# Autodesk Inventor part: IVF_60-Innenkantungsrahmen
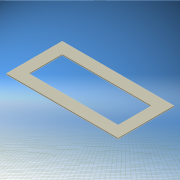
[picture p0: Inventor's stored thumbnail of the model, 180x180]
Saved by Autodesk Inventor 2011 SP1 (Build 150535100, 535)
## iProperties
Created: 2011-05
Part Number: IVF_60-Innenkantungsrahmen
Material: Standard
Document SubType Name: Blech
Designer: Gawin
Mass: 20.8 g
Surface Area: 228.8 cm^2
Volume: 20.8 cm^3
Density: 1 g/cm^3
Sheet Metal Rule: Standard_mm
Sheet Metal Width: 0,000 mm
Sheet Metal Length: 0,000 mm
Sheet Metal Area: 0,000 mm^2
Author: Gawin
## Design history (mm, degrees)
node "Fläche1"
  sketch "Skizze1"
    geometry: L1 (-100, -50)-(100, -50); L2 (100, -50)-(100, 50); L3 (100, 50)-(-100, 50); L4 (-100, 50)-(-100, -50); L5 (-80, 30)-(80, 30); L6 (80, 30)-(80, -30); L7 (80, -30)-(-80, -30); L8 (-80, -30)-(-80, 30); 5 further points
    constraints: 16 end point, 6 perpendicular, 4 midpoint, 2 horizontal, 2 horizontal alignment, 2 vertical alignment
    dimensions: "d0" = 200 distance of L2.end L3.end; "d1" = 100 distance of L3.end L1.start; "d2" = 20 distance between parallel lines of L5 L3; "d3" = 20 distance between parallel lines of L8 L4 (= d2)
node "Konturlasche1"
  sketch "Skizze2"
    geometry: L1 (80, 0)-(80, -12); L2 (80, -12)-(71, -12); 1 further point
    constraints: 4 end point, 1 perpendicular, 1 vertical
    dimensions: "d5" = 12 distance of L1.start L1.end; "d6" = 9 distance of L1.end L2.end
mirror "Spiegeln1"
node "Abwicklung1"
node "Lasche1"
node "Lasche2"
mirror "Spiegeln2"
node "Zurückfaltung1"
node "Volumenkörper1"
feature "Grobblech1" dims "Stärke" = 2 (derived)
feature "Grobblech2" dims "d7" = 0.5, "d8" = 1 (= TiefeBiegungsfreistellung), "d9" = 4 (= MinimalRest), "d10" = 2 (= Biegeradius), "d11" = 2 (= Biegeradius), "d12" = 2, "d13" = 8 (= GrößeEckenfreistellung), "d14" = 2 (= Abstandsgröße), "d15" = 2 (= JacobiRadiusGröße), "Stärke" = 2 (derived), "AbstandVerbindung" = 0.01
feature "Biegung1" dims "d7" = 0.5, "d8" = 1 (= TiefeBiegungsfreistellung), "d9" = 4 (= MinimalRest), "d10" = 2 (= Biegeradius), "d11" = 2 (= Biegeradius), "d12" = 2, "Stärke" = 2 (derived), "AbstandVerbindung" = 0.01
feature "Ecke1" dims "d12" = 2, "d13" = 8 (= GrößeEckenfreistellung), "d14" = 2 (= Abstandsgröße), "d15" = 2 (= JacobiRadiusGröße)
sketch "Skizze3"
  geometry: L1 (144.5, 0)-(21.5, 0); L2 (21.5, 0)-(21.5, -14); L3 (21.5, -14)-(144.5, -14); L4 (144.5, -14)-(144.5, 0)
  constraints: 8 end point
feature "Grobblech3" dims "d16" = 2 (= BreiteBiegungsfreistellung), "d17" = 1 (= TiefeBiegungsfreistellung), "d18" = 4 (= MinimalRest), "d19" = 2 (= Biegeradius), "d20" = 21.5, "d21" = 21.5, "d22" = 14, "d23" = 90 deg, "d24" = 2 (= Biegeradius), "d25" = 8 (= GrößeEckenfreistellung), "d26" = 2 (= Abstandsgröße), "d27" = 2 (= JacobiRadiusGröße), "Stärke" = 2 (derived), "AbstandVerbindung" = 0.01
feature "Biegung2" dims "d16" = 2 (= BreiteBiegungsfreistellung), "d17" = 1 (= TiefeBiegungsfreistellung), "d18" = 4 (= MinimalRest), "d19" = 2 (= Biegeradius), "d22" = 14, "d23" = 90 deg, "d24" = 2 (= Biegeradius), "Stärke" = 2 (derived), "AbstandVerbindung" = 0.01
feature "Ecke2" dims "d22" = 14, "d23" = 90 deg, "d25" = 8 (= GrößeEckenfreistellung), "d26" = 2 (= Abstandsgröße), "d27" = 2 (= JacobiRadiusGröße)
sketch "Skizze4"
  geometry: L1 (0, -6)-(123, -6); L2 (123, -6)-(123, 0); 2 other entities
  constraints: 4 end point, 4 other
feature "Grobblech4" dims "d28" = 2 (= BreiteBiegungsfreistellung), "d29" = 1 (= TiefeBiegungsfreistellung), "d30" = 4 (= MinimalRest), "d31" = 2 (= Biegeradius), "d32" = 6, "d33" = 90 deg, "d34" = 2 (= Biegeradius), "d35" = 8 (= GrößeEckenfreistellung), "d36" = 2 (= Abstandsgröße), "d37" = 2 (= JacobiRadiusGröße), "Stärke" = 2 (derived), "AbstandVerbindung" = 0.01
feature "Biegung3" dims "d28" = 2 (= BreiteBiegungsfreistellung), "d29" = 1 (= TiefeBiegungsfreistellung), "d30" = 4 (= MinimalRest), "d31" = 2 (= Biegeradius), "d32" = 6, "d33" = 90 deg, "d34" = 2 (= Biegeradius), "Stärke" = 2 (derived), "AbstandVerbindung" = 0.01
feature "Ecke3" dims "d32" = 6, "d33" = 90 deg, "d35" = 8 (= GrößeEckenfreistellung), "d36" = 2 (= Abstandsgröße), "d37" = 2 (= JacobiRadiusGröße)
other parameters: "KFaktor" = 4.4, "Biegeradius" = 2 (= Stärke), "BreiteBiegungsfreistellung" = 2 (= Stärke), "TiefeBiegungsfreistellung" = 1 (= 0.5 x Stärke), "GrößeEckenfreistellung" = 8 (= 4 x Stärke), "MinimalRest" = 4 (= 2 x Stärke), "Übergangsradius" = 2 (= Biegeradius), "JacobiRadiusGröße" = 2 (= Biegeradius), "Abstandsgröße" = 2 (= Stärke), "d4" = 2 (= Biegeradius)
